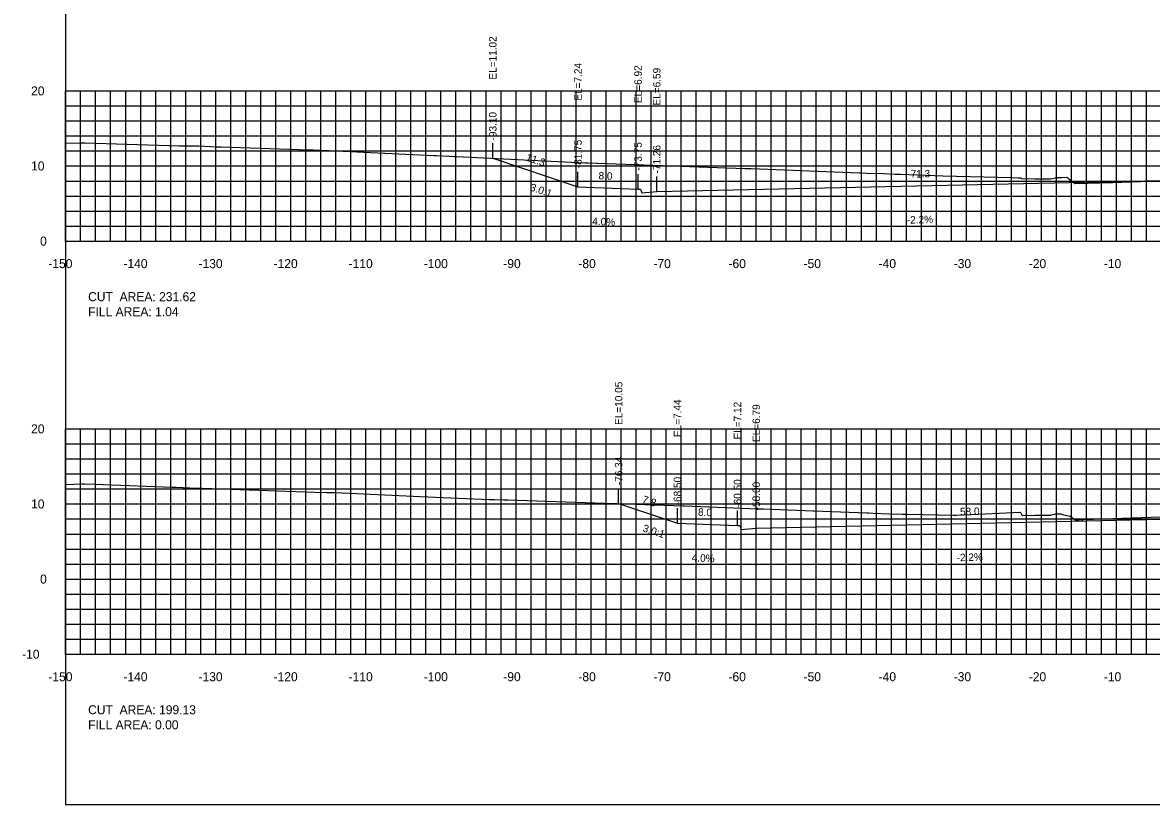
# Model space of a CAD drawing. Extents: x 1797419 to 1809236, y 248759 to 251512.
# Drawn here: x 1804855.3 to 1805005.6, y 250854.9 to 250959 of the extents above; entities that cross this region are included whole.
import ezdxf

# ---------------------------------------------------------------- set-up
doc = ezdxf.new("R2010")
doc.units = 0
for name, color, linetype in [('10', 7, 'Continuous'), ('3', 7, 'Continuous'), ('31', 7, 'Continuous'), ('4', 7, 'Continuous'), ('60', 7, 'Continuous'), ('ANNO-TXT', 7, 'Continuous'), ('CL-CNST', 7, 'Continuous'), ('Level 62', 7, 'Continuous'), ('M-ROADS', 7, 'Continuous')]:
    doc.layers.add(name, color=color, linetype=linetype)

msp = doc.modelspace()

# ---------------------------------------------------------------- linework, layer by layer
for p, q in [((1804917.9, 250940.91), (1804917.9, 250942.91)), ((1804929.25, 250937.13), (1804929.25, 250939.13)), ((1804937.25, 250936.81), (1804937.25, 250938.81)), ((1804939.74, 250936.48), (1804939.74, 250938.48)), ((1804934.67, 250894.94), (1804934.67, 250896.94)), ((1804942.5, 250892.33), (1804942.5, 250894.33)), ((1804950.5, 250892.01), (1804950.5, 250894.01)), ((1804953, 250891.68), (1804953, 250893.68))]:
    msp.add_line(p, q)
msp.add_lwpolyline([(1804861, 250854.89), (1805161, 250854.89), (1805161, 251044.89), (1804861, 251044.89)], close=True)
at = {"layer": '60'}
for p, q in [((1804860.94, 250949.89), (1804861, 250949.89)), ((1804861, 250929.89), (1804861, 250949.89)), ((1804860.94, 250939.89), (1804861, 250939.89)), ((1804860.94, 250929.89), (1804861, 250929.89)), ((1804861, 250929.89), (1805161, 250929.89)), ((1804861, 250929.83), (1804861, 250929.89)), ((1804871, 250929.83), (1804871, 250929.89)), ((1804881, 250929.83), (1804881, 250929.89)), ((1804891, 250929.83), (1804891, 250929.89)), ((1804901, 250929.83), (1804901, 250929.89)), ((1804911, 250929.83), (1804911, 250929.89)), ((1804921, 250929.83), (1804921, 250929.89)), ((1804931, 250929.83), (1804931, 250929.89)), ((1804941, 250929.83), (1804941, 250929.89)), ((1804951, 250929.83), (1804951, 250929.89)), ((1804961, 250929.83), (1804961, 250929.89)), ((1804971, 250929.83), (1804971, 250929.89)), ((1804981, 250929.83), (1804981, 250929.89)), ((1804991, 250929.83), (1804991, 250929.89)), ((1805001, 250929.83), (1805001, 250929.89)), ((1804860.94, 250904.89), (1804861, 250904.89)), ((1804861, 250874.89), (1804861, 250904.89)), ((1804860.94, 250894.89), (1804861, 250894.89)), ((1804860.94, 250884.89), (1804861, 250884.89)), ((1804860.94, 250874.89), (1804861, 250874.89)), ((1804861, 250874.89), (1805161, 250874.89)), ((1804861, 250874.83), (1804861, 250874.89)), ((1804871, 250874.83), (1804871, 250874.89)), ((1804881, 250874.83), (1804881, 250874.89)), ((1804891, 250874.83), (1804891, 250874.89)), ((1804901, 250874.83), (1804901, 250874.89)), ((1804911, 250874.83), (1804911, 250874.89)), ((1804921, 250874.83), (1804921, 250874.89)), ((1804931, 250874.83), (1804931, 250874.89)), ((1804941, 250874.83), (1804941, 250874.89)), ((1804951, 250874.83), (1804951, 250874.89)), ((1804961, 250874.83), (1804961, 250874.89)), ((1804971, 250874.83), (1804971, 250874.89)), ((1804981, 250874.83), (1804981, 250874.89)), ((1804991, 250874.83), (1804991, 250874.89)), ((1805001, 250874.83), (1805001, 250874.89))]:
    msp.add_line(p, q, dxfattribs=at)
at = {"layer": 'CL-CNST'}
for points in [[(1804917.9, 250940.91), (1804929.25, 250937.13), (1804937.25, 250936.81), (1804937.58, 250936.81), (1804937.74, 250936.31), (1804939.74, 250936.48), (1805011, 250938.04), (1805081, 250936.5), (1805083, 250936.34), (1805083.17, 250936.84), (1805083.5, 250936.84), (1805085.5, 250936.92), (1805090.5, 250937.02), (1805091.5, 250937.06), (1805094.65, 250938.11)], [(1804934.67, 250894.94), (1804942.5, 250892.33), (1804950.5, 250892.01), (1804950.83, 250892.01), (1804951, 250891.51), (1804953, 250891.68), (1805011, 250892.95), (1805075.08, 250891.54), (1805077.08, 250891.38), (1805077.24, 250891.88), (1805077.57, 250891.88), (1805079.57, 250891.96), (1805084.57, 250892.06), (1805085.57, 250892.1), (1805090.24, 250893.65)]]:
    msp.add_lwpolyline(points, dxfattribs=at)
at = {"layer": 'Level 62'}
for p, q in [((1804861, 250949.89), (1805161, 250949.89)), ((1804861, 250929.89), (1804861, 250949.89)), ((1804863, 250929.89), (1804863, 250949.89)), ((1804865, 250929.89), (1804865, 250949.89)), ((1804867, 250929.89), (1804867, 250949.89)), ((1804869, 250929.89), (1804869, 250949.89)), ((1804871, 250929.89), (1804871, 250949.89)), ((1804873, 250929.89), (1804873, 250949.89)), ((1804875, 250929.89), (1804875, 250949.89)), ((1804877, 250929.89), (1804877, 250949.89)), ((1804879, 250929.89), (1804879, 250949.89)), ((1804881, 250929.89), (1804881, 250949.89)), ((1804883, 250929.89), (1804883, 250949.89)), ((1804885, 250929.89), (1804885, 250949.89)), ((1804887, 250929.89), (1804887, 250949.89)), ((1804889, 250929.89), (1804889, 250949.89)), ((1804891, 250929.89), (1804891, 250949.89)), ((1804893, 250929.89), (1804893, 250949.89)), ((1804895, 250929.89), (1804895, 250949.89)), ((1804897, 250929.89), (1804897, 250949.89)), ((1804899, 250929.89), (1804899, 250949.89)), ((1804901, 250929.89), (1804901, 250949.89)), ((1804903, 250929.89), (1804903, 250949.89)), ((1804905, 250929.89), (1804905, 250949.89)), ((1804907, 250929.89), (1804907, 250949.89)), ((1804909, 250929.89), (1804909, 250949.89)), ((1804911, 250929.89), (1804911, 250949.89)), ((1804913, 250929.89), (1804913, 250949.89)), ((1804915, 250929.89), (1804915, 250949.89)), ((1804917, 250929.89), (1804917, 250949.89)), ((1804919, 250929.89), (1804919, 250949.89)), ((1804921, 250929.89), (1804921, 250949.89)), ((1804923, 250929.89), (1804923, 250949.89)), ((1804925, 250929.89), (1804925, 250949.89)), ((1804927, 250929.89), (1804927, 250949.89)), ((1804929, 250929.89), (1804929, 250949.89)), ((1804931, 250929.89), (1804931, 250949.89)), ((1804933, 250929.89), (1804933, 250949.89)), ((1804935, 250929.89), (1804935, 250949.89)), ((1804937, 250929.89), (1804937, 250949.89)), ((1804939, 250929.89), (1804939, 250949.89)), ((1804941, 250929.89), (1804941, 250949.89)), ((1804943, 250929.89), (1804943, 250949.89)), ((1804945, 250929.89), (1804945, 250949.89)), ((1804947, 250929.89), (1804947, 250949.89)), ((1804949, 250929.89), (1804949, 250949.89)), ((1804951, 250929.89), (1804951, 250949.89)), ((1804953, 250929.89), (1804953, 250949.89)), ((1804955, 250929.89), (1804955, 250949.89)), ((1804957, 250929.89), (1804957, 250949.89)), ((1804959, 250929.89), (1804959, 250949.89)), ((1804961, 250929.89), (1804961, 250949.89)), ((1804963, 250929.89), (1804963, 250949.89)), ((1804965, 250929.89), (1804965, 250949.89)), ((1804967, 250929.89), (1804967, 250949.89)), ((1804969, 250929.89), (1804969, 250949.89)), ((1804971, 250929.89), (1804971, 250949.89)), ((1804973, 250929.89), (1804973, 250949.89)), ((1804975, 250929.89), (1804975, 250949.89)), ((1804977, 250929.89), (1804977, 250949.89)), ((1804979, 250929.89), (1804979, 250949.89)), ((1804981, 250929.89), (1804981, 250949.89)), ((1804983, 250929.89), (1804983, 250949.89)), ((1804985, 250929.89), (1804985, 250949.89)), ((1804987, 250929.89), (1804987, 250949.89)), ((1804989, 250929.89), (1804989, 250949.89)), ((1804991, 250929.89), (1804991, 250949.89)), ((1804993, 250929.89), (1804993, 250949.89)), ((1804995, 250929.89), (1804995, 250949.89)), ((1804997, 250929.89), (1804997, 250949.89)), ((1804999, 250929.89), (1804999, 250949.89)), ((1805001, 250929.89), (1805001, 250949.89)), ((1805003, 250929.89), (1805003, 250949.89)), ((1805005, 250929.89), (1805005, 250949.89)), ((1804861, 250947.89), (1805161, 250947.89)), ((1804861, 250945.89), (1805161, 250945.89)), ((1804861, 250943.89), (1805161, 250943.89)), ((1804861, 250941.89), (1805161, 250941.89)), ((1804861, 250939.89), (1805161, 250939.89)), ((1804861, 250937.89), (1805161, 250937.89)), ((1804861, 250935.89), (1805161, 250935.89)), ((1804861, 250933.89), (1805161, 250933.89)), ((1804861, 250931.89), (1805161, 250931.89)), ((1804861, 250929.89), (1805161, 250929.89)), ((1804861, 250904.89), (1805161, 250904.89)), ((1804861, 250874.89), (1804861, 250904.89)), ((1804863, 250874.89), (1804863, 250904.89)), ((1804865, 250874.89), (1804865, 250904.89)), ((1804867, 250874.89), (1804867, 250904.89)), ((1804869, 250874.89), (1804869, 250904.89)), ((1804871, 250874.89), (1804871, 250904.89)), ((1804873, 250874.89), (1804873, 250904.89)), ((1804875, 250874.89), (1804875, 250904.89)), ((1804877, 250874.89), (1804877, 250904.89)), ((1804879, 250874.89), (1804879, 250904.89)), ((1804881, 250874.89), (1804881, 250904.89)), ((1804883, 250874.89), (1804883, 250904.89)), ((1804885, 250874.89), (1804885, 250904.89)), ((1804887, 250874.89), (1804887, 250904.89)), ((1804889, 250874.89), (1804889, 250904.89)), ((1804891, 250874.89), (1804891, 250904.89)), ((1804893, 250874.89), (1804893, 250904.89)), ((1804895, 250874.89), (1804895, 250904.89)), ((1804897, 250874.89), (1804897, 250904.89)), ((1804899, 250874.89), (1804899, 250904.89)), ((1804901, 250874.89), (1804901, 250904.89)), ((1804903, 250874.89), (1804903, 250904.89)), ((1804905, 250874.89), (1804905, 250904.89)), ((1804907, 250874.89), (1804907, 250904.89)), ((1804909, 250874.89), (1804909, 250904.89)), ((1804911, 250874.89), (1804911, 250904.89)), ((1804913, 250874.89), (1804913, 250904.89)), ((1804915, 250874.89), (1804915, 250904.89)), ((1804917, 250874.89), (1804917, 250904.89)), ((1804919, 250874.89), (1804919, 250904.89)), ((1804921, 250874.89), (1804921, 250904.89)), ((1804923, 250874.89), (1804923, 250904.89)), ((1804925, 250874.89), (1804925, 250904.89)), ((1804927, 250874.89), (1804927, 250904.89)), ((1804929, 250874.89), (1804929, 250904.89)), ((1804931, 250874.89), (1804931, 250904.89)), ((1804933, 250874.89), (1804933, 250904.89)), ((1804935, 250874.89), (1804935, 250904.89)), ((1804937, 250874.89), (1804937, 250904.89)), ((1804939, 250874.89), (1804939, 250904.89)), ((1804941, 250874.89), (1804941, 250904.89)), ((1804943, 250874.89), (1804943, 250904.89)), ((1804945, 250874.89), (1804945, 250904.89)), ((1804947, 250874.89), (1804947, 250904.89)), ((1804949, 250874.89), (1804949, 250904.89)), ((1804951, 250874.89), (1804951, 250904.89)), ((1804953, 250874.89), (1804953, 250904.89)), ((1804955, 250874.89), (1804955, 250904.89)), ((1804957, 250874.89), (1804957, 250904.89)), ((1804959, 250874.89), (1804959, 250904.89)), ((1804961, 250874.89), (1804961, 250904.89)), ((1804963, 250874.89), (1804963, 250904.89)), ((1804965, 250874.89), (1804965, 250904.89)), ((1804967, 250874.89), (1804967, 250904.89)), ((1804969, 250874.89), (1804969, 250904.89)), ((1804971, 250874.89), (1804971, 250904.89)), ((1804973, 250874.89), (1804973, 250904.89)), ((1804975, 250874.89), (1804975, 250904.89)), ((1804977, 250874.89), (1804977, 250904.89)), ((1804979, 250874.89), (1804979, 250904.89)), ((1804981, 250874.89), (1804981, 250904.89)), ((1804983, 250874.89), (1804983, 250904.89)), ((1804985, 250874.89), (1804985, 250904.89)), ((1804987, 250874.89), (1804987, 250904.89)), ((1804989, 250874.89), (1804989, 250904.89)), ((1804991, 250874.89), (1804991, 250904.89)), ((1804993, 250874.89), (1804993, 250904.89)), ((1804995, 250874.89), (1804995, 250904.89)), ((1804997, 250874.89), (1804997, 250904.89)), ((1804999, 250874.89), (1804999, 250904.89)), ((1805001, 250874.89), (1805001, 250904.89)), ((1805003, 250874.89), (1805003, 250904.89)), ((1805005, 250874.89), (1805005, 250904.89)), ((1804861, 250902.89), (1805161, 250902.89)), ((1804861, 250900.89), (1805161, 250900.89)), ((1804861, 250898.89), (1805161, 250898.89)), ((1804861, 250896.89), (1805161, 250896.89)), ((1804861, 250894.89), (1805161, 250894.89)), ((1804861, 250892.89), (1805161, 250892.89)), ((1804861, 250890.89), (1805161, 250890.89)), ((1804861, 250888.89), (1805161, 250888.89)), ((1804861, 250886.89), (1805161, 250886.89)), ((1804861, 250884.89), (1805161, 250884.89)), ((1804861, 250882.89), (1805161, 250882.89)), ((1804861, 250880.89), (1805161, 250880.89)), ((1804861, 250878.89), (1805161, 250878.89)), ((1804861, 250876.89), (1805161, 250876.89)), ((1804861, 250874.89), (1805161, 250874.89))]:
    msp.add_line(p, q, dxfattribs=at)
at = {"layer": 'M-ROADS'}
for points in [[(1804861, 250942.92), (1804862.88, 250942.96), (1804862.92, 250942.96), (1804863.25, 250942.97), (1804863.29, 250942.97), (1804863.59, 250942.96), (1804876.19, 250942.59), (1804878.7, 250942.55), (1804878.75, 250942.55), (1804881.01, 250942.46), (1804881.54, 250942.44), (1804881.73, 250942.44), (1804893.42, 250942.04), (1804893.84, 250942.04), (1804894.02, 250942.04), (1804896.07, 250941.97), (1804910.06, 250941.28), (1804910.34, 250941.27), (1804912.1, 250941.19), (1804912.78, 250941.16), (1804912.79, 250941.16), (1804912.96, 250941.15), (1804913.07, 250941.14), (1804930.2, 250940.33), (1804930.22, 250940.33), (1804930.56, 250940.33), (1804931.82, 250940.27), (1804931.88, 250940.27), (1804947.8, 250939.69), (1804951.53, 250939.56), (1804951.99, 250939.55), (1804952.32, 250939.54), (1804966.77, 250938.96), (1804967.01, 250938.96), (1804967.74, 250938.94), (1804969.97, 250938.87), (1804971.5, 250938.8), (1804971.63, 250938.8), (1804972.2, 250938.78), (1804977.84, 250938.6), (1804987, 250938.34), (1804987.05, 250938.34), (1804987.87, 250938.33), (1804987.93, 250938.33), (1804987.93, 250938.33), (1804987.95, 250938.33), (1804988.28, 250938.33), (1804988.35, 250938.21), (1804990.09, 250938.17), (1804992.17, 250938.16), (1804992.21, 250938.2), (1804992.86, 250938.32), (1804992.99, 250938.34), (1804993.29, 250938.34), (1804993.34, 250938.34), (1804993.63, 250938.34), (1804993.7, 250938.34), (1804993.73, 250938.34), (1804994.28, 250938.39), (1804994.5, 250938.3), (1804994.83, 250938.05), (1804995.11, 250937.82), (1804995.43, 250937.56), (1804997.04, 250937.59), (1804997.09, 250937.6), (1804997.12, 250937.6), (1805000.44, 250937.71), (1805009.31, 250938.01)], [(1804861, 250897.48), (1804863.19, 250897.55), (1804863.56, 250897.56), (1804864.84, 250897.53), (1804875.18, 250897.12), (1804875.67, 250897.11), (1804876.61, 250897.09), (1804876.65, 250897.09), (1804878.47, 250897.01), (1804878.56, 250897), (1804879.18, 250896.99), (1804894.2, 250896.47), (1804895.78, 250896.41), (1804896.05, 250896.41), (1804896.21, 250896.41), (1804896.38, 250896.41), (1804896.87, 250896.4), (1804896.9, 250896.4), (1804908.24, 250895.87), (1804917.43, 250895.49), (1804918.04, 250895.49), (1804918.09, 250895.48), (1804919.33, 250895.44), (1804919.38, 250895.44), (1804919.9, 250895.43), (1804934.06, 250894.96), (1804934.42, 250894.95), (1804943.25, 250894.65), (1804943.43, 250894.65), (1804953.22, 250894.26), (1804953.52, 250894.26), (1804953.97, 250894.25), (1804960.59, 250893.98), (1804960.72, 250893.98), (1804967.72, 250893.69), (1804967.93, 250893.69), (1804968.53, 250893.68), (1804970.69, 250893.58), (1804972.44, 250893.54), (1804972.59, 250893.54), (1804973.14, 250893.53), (1804979.28, 250893.39), (1804979.51, 250893.39), (1804979.63, 250893.39), (1804981.59, 250893.51), (1804981.64, 250893.51), (1804988.16, 250893.79), (1804988.24, 250893.72), (1804988.4, 250893.37), (1804990.17, 250893.38), (1804990.37, 250893.38), (1804992.18, 250893.39), (1804992.25, 250893.38), (1804992.31, 250893.44), (1804992.77, 250893.54), (1804992.86, 250893.56), (1804992.94, 250893.56), (1804993.22, 250893.56), (1804993.31, 250893.56), (1804993.56, 250893.56), (1804993.74, 250893.5), (1804994.83, 250893.27), (1804995.25, 250892.97), (1804995.55, 250892.75), (1804996.38, 250892.81), (1804996.38, 250892.81), (1804996.42, 250892.8), (1804996.47, 250892.79), (1804996.49, 250892.78), (1804996.52, 250892.79), (1804996.57, 250892.82), (1804996.58, 250892.82), (1804996.58, 250892.82), (1804997.91, 250892.86), (1805009.41, 250893.25)]]:
    msp.add_lwpolyline(points, dxfattribs=at)

# ---------------------------------------------------------------- texts
for p in [(1804922.78, 250936.65), (1804937.79, 250891.26)]:
    msp.add_text('3.0:1', height=1, rotation=341.5651).set_placement(p)
at = {"layer": '10'}
for s, p in [('-150', (1804858.7, 250926.29)), ('-140', (1804868.7, 250926.29)), ('-130', (1804878.7, 250926.29)), ('-120', (1804888.7, 250926.29)), ('-110', (1804898.7, 250926.29)), ('-100', (1804908.7, 250926.29)), ('-90', (1804919.3, 250926.29)), ('-80', (1804929.3, 250926.29)), ('-70', (1804939.3, 250926.29)), ('-60', (1804949.3, 250926.29)), ('-50', (1804959.3, 250926.29)), ('-40', (1804969.3, 250926.29)), ('-30', (1804979.3, 250926.29)), ('-20', (1804989.3, 250926.29)), ('-10', (1804999.3, 250926.29)), ('-150', (1804858.7, 250871.29)), ('-140', (1804868.7, 250871.29)), ('-130', (1804878.7, 250871.29)), ('-120', (1804888.7, 250871.29)), ('-110', (1804898.7, 250871.29)), ('-100', (1804908.7, 250871.29)), ('-90', (1804919.3, 250871.29)), ('-80', (1804929.3, 250871.29)), ('-70', (1804939.3, 250871.29)), ('-60', (1804949.3, 250871.29)), ('-50', (1804959.3, 250871.29)), ('-40', (1804969.3, 250871.29)), ('-30', (1804979.3, 250871.29)), ('-20', (1804989.3, 250871.29)), ('-10', (1804999.3, 250871.29))]:
    msp.add_text(s, height=1.2, dxfattribs=at).set_placement(p)
at = {"layer": '3'}
for s, p in [('EL=11.02', (1804918.4, 250951.39)), ('EL=7.24', (1804929.75, 250948.59)), ('EL=6.92', (1804937.75, 250948.27)), ('EL=6.59', (1804940.24, 250947.94)), ('-93.10', (1804918.4, 250943.29)), ('-81.75', (1804929.75, 250939.59)), ('-73.75', (1804937.75, 250939.27)), ('-71.26', (1804940.24, 250938.89)), ('EL=10.05', (1804935.17, 250905.41)), ('EL=7.44', (1804943, 250903.79)), ('EL=7.12', (1804951, 250903.47)), ('EL=6.79', (1804953.5, 250903.14)), ('-76.34', (1804935.17, 250897.4)), ('-68.50', (1804943, 250894.71)), ('-60.50', (1804951, 250894.39)), ('-58.00', (1804953.5, 250894.05))]:
    msp.add_text(s, height=1, rotation=90, dxfattribs=at).set_placement(p)
at = {"layer": '31'}
for s, p in [('20', (1804856.4, 250949.29)), ('10', (1804856.4, 250939.29)), ('0', (1804857.6, 250929.29)), ('20', (1804856.4, 250904.29)), ('10', (1804856.4, 250894.29)), ('0', (1804857.6, 250884.29)), ('-10', (1804855.2, 250874.29))]:
    msp.add_text(s, height=1.2, dxfattribs=at).set_placement(p)
at = {"layer": '4'}
for s, rotation, p in [('11.3', 341.5651, (1804922.23, 250940.63)), ('8.0', 357.7094, (1804931.97, 250938.12)), ('71.3', 1.2603, (1804973.57, 250938.32)), ('4.0%', 357.7094, (1804931.14, 250932.05)), ('-2.2%', 1.2603, (1804973.07, 250932.21)), ('7.8', 341.5651, (1804937.72, 250895.09)), ('8.0', 357.7094, (1804945.23, 250893.32)), ('58.0', 1.2603, (1804980.16, 250893.37)), ('4.0%', 357.7094, (1804944.39, 250887.25)), ('-2.2%', 1.2603, (1804979.7, 250887.26))]:
    msp.add_text(s, height=1, rotation=rotation, dxfattribs=at).set_placement(p)
at = {"layer": '60'}
for p in [(1804861, 250929.89), (1804861, 250874.89)]:
    msp.add_text('-', height=0.0001, dxfattribs=at).set_placement(p)
at = {"layer": 'ANNO-TXT'}
for s, p in [('CUT  AREA: 231.62', (1804864, 250921.89)), ('FILL AREA: 1.04', (1804864, 250919.89)), ('CUT  AREA: 199.13', (1804864, 250866.89)), ('FILL AREA: 0.00', (1804864, 250864.89))]:
    msp.add_text(s, height=1.2, dxfattribs=at).set_placement(p)

doc.saveas('drawing.dxf')
